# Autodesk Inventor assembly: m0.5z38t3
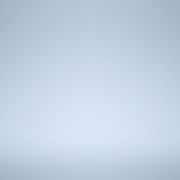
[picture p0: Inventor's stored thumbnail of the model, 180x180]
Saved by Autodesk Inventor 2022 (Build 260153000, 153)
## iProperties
Created: 2024-10
Part Number: m0.5z38t3
Document SubType Name: Assembly
Designer: shimizu
Author: shimizu
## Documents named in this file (1)
- C:\Users\shimizu\Documents\卒論2024\3DCAD\ギアボックス\m0.5z38t3.iam
